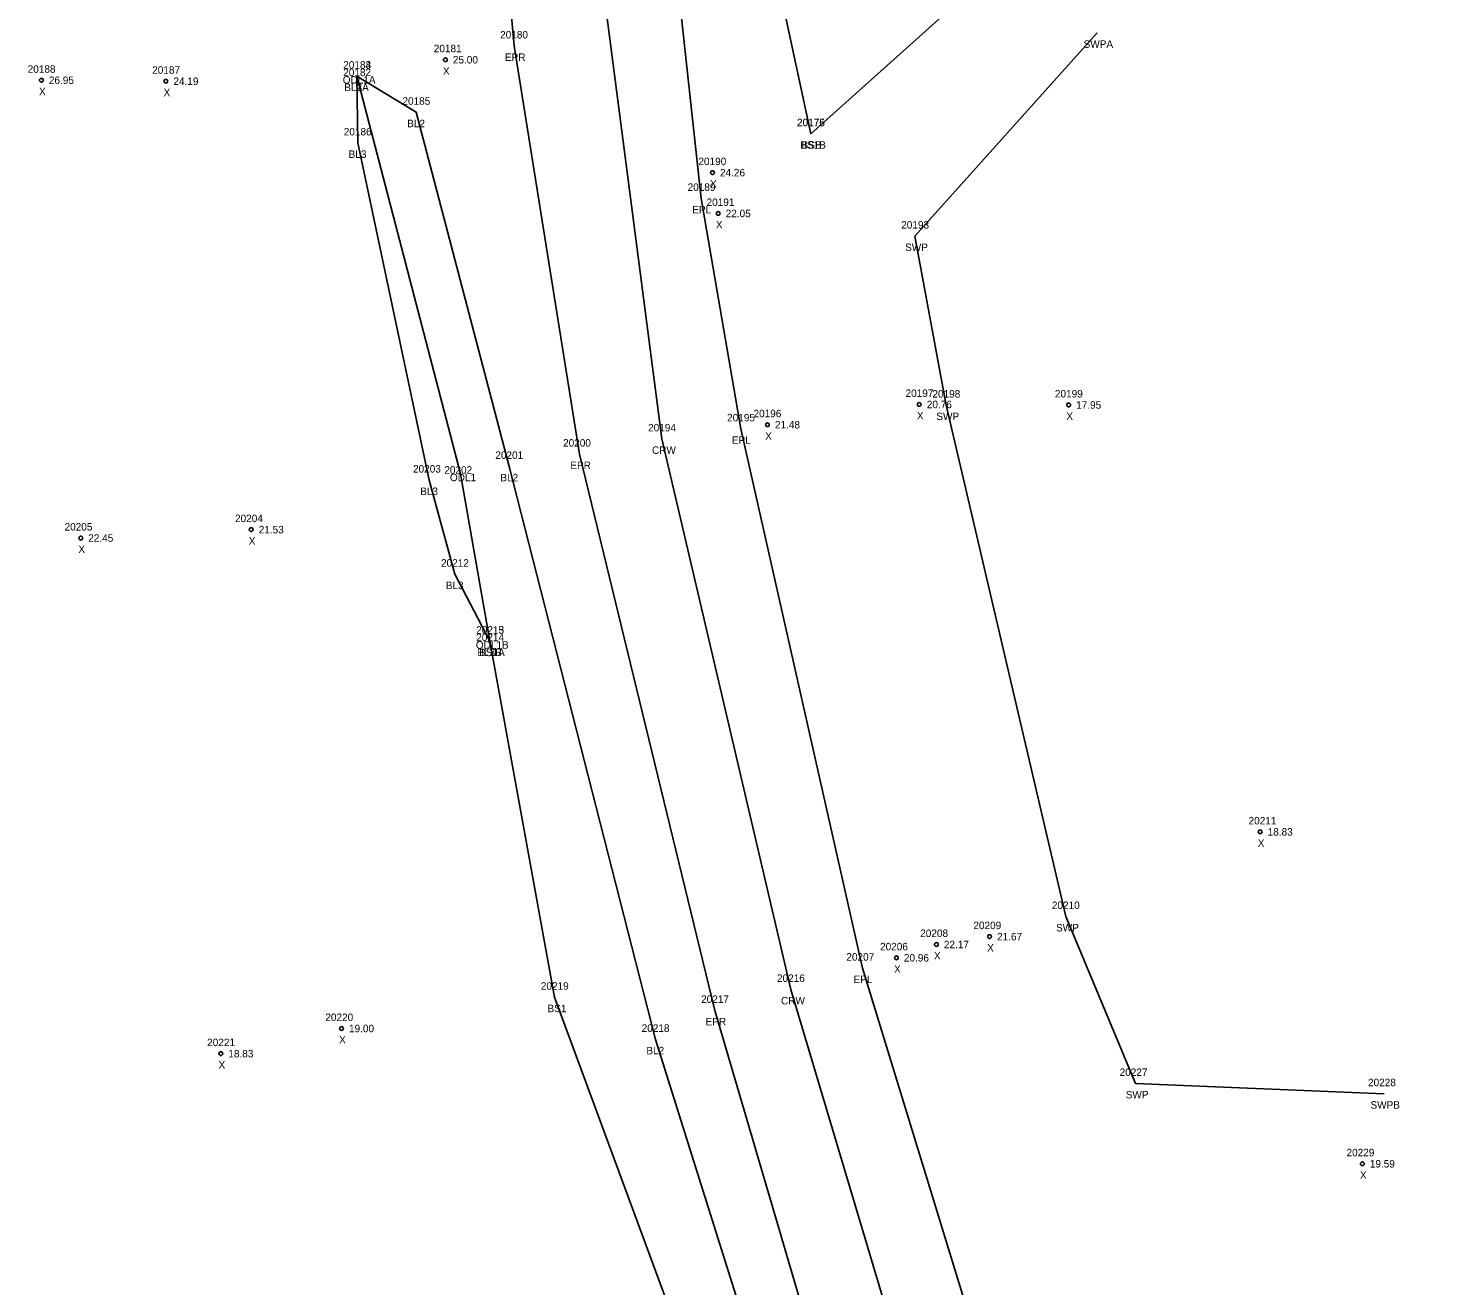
# Model space of a CAD drawing. Extents: x 2432729 to 2433340, y 684958 to 688103.
# Drawn here: x 2432855.1 to 2433043.1, y 686887.8 to 687055.8 of the extents above; entities that cross this region are included whole.
import ezdxf

# ---------------------------------------------------------------- set-up
doc = ezdxf.new("R2010")
doc.units = 0
for name, color, linetype in [('RD_DTM_BkLn1', 7, 'Continuous'), ('RD_DTM_BkLn2', 7, 'Continuous'), ('RD_EX_H2O', 7, 'Continuous'), ('RD_EX_H2O_txCode', 7, 'Continuous'), ('RD_EX_Road', 7, 'Continuous'), ('RD_EX_Road_txCode', 7, 'Continuous'), ('RD_Sketch8', 7, 'Continuous'), ('RD_SMD_Locator', 7, 'Continuous'), ('RD_SMD_Misc', 7, 'Continuous')]:
    doc.layers.add(name, color=color, linetype=linetype)

msp = doc.modelspace()

# ---------------------------------------------------------------- linework, layer by layer
at = {"layer": 'RD_DTM_BkLn1'}
for points in [[(2432926.02, 687213.66), (2432924.35, 687158.94), (2432925.68, 687108.84), (2432939.7, 687000.92), (2432956.93, 686927.39), (2432975, 686866.8), (2433007.19, 686769.33), (2433041.66, 686669.67), (2433075.97, 686569.51), (2433108.49, 686474.01), (2433123.82, 686426.48), (2433137.99, 686374.7), (2433148.76, 686320.1), (2433154.8, 686269.16), (2433155.78, 686212.93), (2433152.37, 686164.52), (2433145.67, 686113.9), (2433140.38, 686078.83)], [(2432898.98, 687049.37), (2432906.9, 687044.55), (2432919.33, 686997.25), (2432938.84, 686920.72), (2432957.15, 686862.46), (2432990.45, 686763.71), (2433024.84, 686664.51), (2433058.68, 686562.8), (2433090.41, 686467.11), (2433107.21, 686420.87), (2433120.26, 686369.86), (2433132.05, 686313.5), (2433136.59, 686267.4), (2433133.92, 686213.17), (2433133.74, 686165.58), (2433125.69, 686115.89), (2433123.08, 686088.41), (2433128.09, 686081.14)], [(2432898.98, 687049.37), (2432899.08, 687040.45), (2432908.62, 686995.42), (2432912.05, 686982.85), (2432916.74, 686973.9)]]:
    msp.add_lwpolyline(points, dxfattribs=at)
at = {"layer": 'RD_DTM_BkLn2'}
msp.add_line((2433038.07, 687112), (2432959.59, 687041.68), dxfattribs=at)
for points in [[(2432956.03, 687234.5), (2432952.13, 687211.69), (2432949.74, 687186.09), (2432947.53, 687157.65), (2432946.61, 687110.22), (2432949.21, 687089.9), (2432959.59, 687041.68)], [(2432916.74, 686973.9), (2432925.37, 686926.35), (2432950.18, 686859.06), (2432982.46, 686761.59), (2433017.67, 686659.38), (2433053.8, 686561.16), (2433080.54, 686460.75), (2433098.39, 686424.64), (2433113.62, 686368.79), (2433123.31, 686312.63), (2433128.29, 686266.56), (2433126.49, 686214.47), (2433123.88, 686164.31), (2433114.46, 686111.82), (2433110.48, 686084.68), (2433120.95, 686072.12)]]:
    msp.add_lwpolyline(points, dxfattribs=at)
at = {"layer": 'RD_EX_H2O'}
for points in [[(2432997.82, 687055.15), (2432973.49, 687028.01), (2432977.67, 687005.43), (2432993.65, 686937.13), (2433002.95, 686914.83), (2433036.11, 686913.46)], [(2432898.98, 687049.37), (2432912.81, 686996.27), (2432916.74, 686973.9)]]:
    msp.add_lwpolyline(points, dxfattribs=at)
at = {"layer": 'RD_EX_Road'}
for points in [[(2432915.64, 687215.4), (2432913.86, 687159.12), (2432915.08, 687107.55), (2432919.97, 687053.4), (2432928.7, 686998.89), (2432946.77, 686924.59), (2432964.57, 686864), (2432997.3, 686766.34), (2433031.44, 686666.38), (2433066.06, 686565.78), (2433098.73, 686469.74), (2433113.88, 686422.91), (2433127.93, 686372.14), (2433139.1, 686314.76), (2433144.47, 686268.02), (2433145.44, 686213), (2433142.32, 686164.92), (2433135.44, 686115.75), (2433128.09, 686081.14)], [(2432937.12, 687213.43), (2432935.51, 687158.7), (2432936.54, 687110.38), (2432944.97, 687033.04), (2432950.24, 687002.26), (2432966.49, 686930.23), (2432984.9, 686870.1), (2433011.7, 686787.41), (2433010.33, 686784.51), (2433011.78, 686772.99), (2433015.37, 686760.79), (2433021.02, 686752.9), (2433031.88, 686728.09), (2433052.76, 686670.56), (2433070.23, 686619.38), (2433072.02, 686607.31)]]:
    msp.add_lwpolyline(points, dxfattribs=at)
at = {"layer": 'RD_SMD_Locator'}
for centre, radius in [((2432997.82, 687055.15), 0.001), ((2432910.79, 687051.56), 0.25), ((2432919.97, 687053.4), 0.001), ((2432856.84, 687048.82), 0.25), ((2432873.47, 687048.69), 0.25), ((2432898.98, 687049.37), 0.001), ((2432898.98, 687049.37), 0.001), ((2432898.98, 687049.37), 0.001), ((2432906.9, 687044.55), 0.001), ((2432899.08, 687040.45), 0.001), ((2432959.59, 687041.68), 0.001), ((2432959.59, 687041.68), 0.001), ((2432946.46, 687036.48), 0.25), ((2432944.97, 687033.04), 0.001), ((2432947.22, 687031.03), 0.25), ((2432973.49, 687028.01), 0.001), ((2432974.08, 687005.52), 0.25), ((2432977.67, 687005.43), 0.001), ((2432994.02, 687005.45), 0.25), ((2432953.8, 687002.81), 0.25), ((2432939.7, 687000.92), 0.001), ((2432950.24, 687002.26), 0.001), ((2432919.33, 686997.25), 0.001), ((2432928.7, 686998.89), 0.001), ((2432908.62, 686995.42), 0.001), ((2432912.81, 686996.27), 0.001), ((2432862.1, 686987.68), 0.25), ((2432884.86, 686988.8), 0.25), ((2432912.05, 686982.85), 0.001), ((2432916.74, 686973.9), 0.001), ((2432916.74, 686973.9), 0.001), ((2432916.74, 686973.9), 0.001), ((2433019.6, 686948.43), 0.25), ((2432993.65, 686937.13), 0.001), ((2432976.36, 686933.39), 0.25), ((2432983.46, 686934.44), 0.25), ((2432971.02, 686931.61), 0.25), ((2432966.49, 686930.23), 0.001), ((2432925.37, 686926.35), 0.001), ((2432956.93, 686927.39), 0.001), ((2432946.77, 686924.59), 0.001), ((2432896.92, 686922.17), 0.25), ((2432938.84, 686920.72), 0.001), ((2432880.81, 686918.81), 0.25), ((2433002.95, 686914.83), 0.001), ((2433036.11, 686913.46), 0.001), ((2433033.24, 686904.1), 0.25)]:
    msp.add_circle(centre, radius, dxfattribs=at)

# ---------------------------------------------------------------- texts
at = {"layer": 'RD_EX_H2O_txCode'}
for s, p in [('SWPA', (2432996.02, 687053.15)), ('20182', (2432897.15, 687049.37)), ('ODL1A', (2432897.08, 687048.37)), ('20193', (2432971.66, 687029.01)), ('SWP', (2432972.18, 687026.01)), ('20198', (2432975.83, 687006.43)), ('SWP', (2432976.35, 687003.43)), ('20202', (2432910.65, 686996.27)), ('ODL1', (2432911.4, 686995.27)), ('20214', (2432914.91, 686973.9)), ('ODL1B', (2432914.86, 686972.9)), ('20210', (2432991.78, 686938.13)), ('SWP', (2432992.34, 686935.13)), ('20227', (2433000.83, 686915.83)), ('20228', (2433034, 686914.46)), ('SWP', (2433001.64, 686912.83)), ('SWPB', (2433034.33, 686911.46))]:
    msp.add_text(s, height=1, dxfattribs=at).set_placement(p)
at = {"layer": 'RD_EX_Road_txCode'}
for s, p in [('20180', (2432918.1, 687054.4)), ('EPR', (2432918.75, 687051.4)), ('20189', (2432943.14, 687034.04)), ('EPL', (2432943.76, 687031.04)), ('20195', (2432948.41, 687003.26)), ('20200', (2432926.51, 686999.89)), ('EPL', (2432949.04, 687000.26)), ('EPR', (2432927.48, 686996.89)), ('20207', (2432964.34, 686931.23)), ('EPL', (2432965.29, 686928.23)), ('20217', (2432944.94, 686925.59)), ('EPR', (2432945.54, 686922.59))]:
    msp.add_text(s, height=1, dxfattribs=at).set_placement(p)
at = {"layer": 'RD_Sketch8'}
for s, p in [('20181', (2432909.24, 687052.56)), ('25.00', (2432911.79, 687051.06)), ('20188', (2432855.01, 687049.82)), ('20187', (2432871.64, 687049.69)), ('X', (2432910.47, 687049.56)), ('X', (2432856.53, 687046.82)), ('26.95', (2432857.84, 687048.32)), ('24.19', (2432874.47, 687048.19)), ('X', (2432873.16, 687046.69)), ('20190', (2432944.58, 687037.48)), ('24.26', (2432947.46, 687035.98)), ('X', (2432946.14, 687034.48)), ('20191', (2432945.67, 687032.03)), ('22.05', (2432948.22, 687030.53)), ('X', (2432946.91, 687029.03)), ('20197', (2432972.24, 687006.52)), ('20199', (2432992.19, 687006.45)), ('20196', (2432951.94, 687003.81)), ('20.76', (2432975.08, 687005.02)), ('17.95', (2432995.02, 687004.95)), ('21.48', (2432954.8, 687002.31)), ('X', (2432973.76, 687003.52)), ('X', (2432993.71, 687003.45)), ('X', (2432953.49, 687000.81)), ('20205', (2432859.94, 686988.68)), ('20204', (2432882.7, 686989.8)), ('22.45', (2432863.1, 686987.18)), ('X', (2432884.54, 686986.8)), ('21.53', (2432885.86, 686988.3)), ('X', (2432861.78, 686985.68)), ('20211', (2433018.05, 686949.43)), ('18.83', (2433020.6, 686947.93)), ('X', (2433019.28, 686946.43)), ('20208', (2432974.2, 686934.39)), ('20209', (2432981.3, 686935.44)), ('20206', (2432968.84, 686932.61)), ('22.17', (2432977.36, 686932.89)), ('X', (2432983.14, 686932.44)), ('21.67', (2432984.46, 686933.94)), ('20.96', (2432972.02, 686931.11)), ('X', (2432976.04, 686931.39)), ('X', (2432970.71, 686929.61)), ('20220', (2432894.76, 686923.17)), ('19.00', (2432897.92, 686921.67)), ('20221', (2432878.98, 686919.81)), ('X', (2432896.6, 686920.17)), ('18.83', (2432881.81, 686918.31)), ('X', (2432880.5, 686916.81)), ('20229', (2433031.13, 686905.1)), ('X', (2433032.93, 686902.1)), ('19.59', (2433034.24, 686903.6))]:
    msp.add_text(s, height=1, dxfattribs=at).set_placement(p)
at = {"layer": 'RD_SMD_Misc'}
for s, p in [('20183', (2432897.15, 687050.37)), ('20184', (2432897.15, 687050.37)), ('BL2A', (2432897.29, 687047.37)), ('BL3A', (2432897.29, 687047.37)), ('20185', (2432905.06, 687045.55)), ('20186', (2432897.22, 687041.45)), ('BL2', (2432905.69, 687042.55)), ('20176', (2432957.74, 687042.68)), ('20175', (2432957.76, 687042.68)), ('BS1B', (2432958.18, 687039.68)), ('BSB', (2432958.34, 687039.68)), ('BL3', (2432897.87, 687038.45)), ('20194', (2432937.86, 687001.92)), ('20201', (2432917.46, 686998.25)), ('CRW', (2432938.38, 686998.92)), ('20203', (2432906.47, 686996.42)), ('BL2', (2432918.13, 686995.25)), ('BL3', (2432907.42, 686993.42)), ('20212', (2432910.21, 686983.85)), ('BL3', (2432910.84, 686980.85)), ('20213', (2432914.91, 686974.9)), ('20215', (2432914.91, 686974.9)), ('BL3B', (2432915.06, 686971.9)), ('BS1A', (2432915.31, 686971.9)), ('20216', (2432955.07, 686928.39)), ('20219', (2432923.54, 686927.35)), ('CRW', (2432955.61, 686925.39)), ('BS1', (2432924.43, 686924.35)), ('20218', (2432937, 686921.72)), ('BL2', (2432937.63, 686918.72))]:
    msp.add_text(s, height=1, dxfattribs=at).set_placement(p)

doc.saveas('drawing.dxf')
